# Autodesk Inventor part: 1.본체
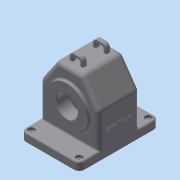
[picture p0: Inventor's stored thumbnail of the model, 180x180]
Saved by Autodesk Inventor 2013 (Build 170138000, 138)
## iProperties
Created: 2016-12
Part Number: 1.본체
Material: 일반
Document SubType Name: Modeling
Designer: Administrator
Density: 1 g/cm^3
Author: Administrator
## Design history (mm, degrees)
sketch "스케치1"
  geometry: L1 (-55, 80)-(-55, 0); L2 (-55, 0)-(55, 0); L3 (55, 0)-(55, 80); L4 (55, 80)-(23.491, 125); L5 (23.491, 125)-(-23.491, 125); L6 (-23.491, 125)-(-55, 80); 3 further points
  constraints: 12 end point, 2 midpoint, 2 parallel, 1 coincident, 1 perpendicular, 1 vertical, 1 vertical alignment
  dimensions: "d0" = 110 distance of L1.end L2.end; "d2" = 80 distance of L2.end L3.end; "d3" = 80 distance of L1.start L1.end; "d4" = 125 distance between parallel lines of L2 L5; "d5" = 35 deg angle of L6 L1; "d6" = 35 deg angle of L4 L3 (derived)
extrude "돌출1" new body sketch "스케치1" stored distance "d7" = 77; taper "d8" = 0 deg
feature "쉘1" dims "d9" = 5
sketch "스케치2"
  geometry: L1 (78.424, 33.5)-(0, 33.5) reference; L2 (80, 38.5)-(0, 38.5) reference; L3 (0, -33.5)-(78.424, -33.5) reference; L4 (0, -38.5)-(80, -38.5) reference; L5 (65, 33.5)-(65, -33.5); L6 (120, 33.5)-(78.424, 33.5) reference; L7 (125, 38.5)-(80, 38.5) reference; L8 (65, 33.5)-(65, 19.5); L9 (65, 19.5)-(92, 19.5); L10 (92, 19.5)-(106, 33.5); 1 further point
  constraints: 8 end point, 4 point on line, 2 perpendicular
  dimensions: "d10" = 65 distance from line of L5 point (0, 0); "d12" = 14 distance between parallel lines of L1 L9; "d13" = 54 diameter of L9.end L5; "d14" = 45 deg angle of L10 L9
revolve "회전1" sketch "스케치2" stored, may be unused: angle "d15" = 90 deg
sketch "스케치3"
  geometry: L1 (-55, 0)-(55, 0) reference; C1 r 37.5 at (0, 65); 2 further points
  constraints: 1 centre point, 1 midpoint, 1 vertical alignment
  dimensions: "d16" = 65 distance of point (0, 0) C1.centre; "d17" = 75 diameter of C1
extrude "돌출2" join sketch "스케치3" distance "d18" = 5; taper "d19" = 0 deg
sketch "스케치4"
  geometry: L1 (-55, 0)-(55, 0) reference; C1 r 31 at (0, 65); 2 further points
  constraints: 1 centre point, 1 midpoint, 1 vertical alignment
  dimensions: "d20" = 65 distance of point (0, 0) C1.centre; "d21" = 62 diameter of C1
extrude "돌출3" join sketch "스케치4" distance "d22" = 10; taper "d23" = 0 deg
hole "구멍1" diameter "d26" = 40; stored, may be unused: countersink angle "d30" = 90 deg, drill point angle "d32" = 118 deg; dims "d24" = 10, "d25" = 10, "d27" = 6, "d28" = 4, "d29" = 2, "d31" = 8
sketch "스케치5" dims "d33" = 58
  geometry: C1 r 20 at (0, 0) reference; 3 further points
  constraints: 2 vertical alignment, 1 coincident, 2 other
hole "구멍2" sketch "스케치5" at (0, 29) diameter "d35" = 2.459; stored, may be unused: countersink angle "d39" = 90 deg, drill point angle "d41" = 118 deg; dims "d36" = 6, "d37" = 4, "d38" = 2, "d40" = 8
sketch "스케치6" dims "d45" = 52
  geometry: C1 r 20 at (0, 0) reference; 3 further points
  constraints: 2 vertical alignment, 1 coincident, 2 other
hole "구멍3" sketch "스케치6" at (0, 26) diameter "d47" = 2.459; stored, may be unused: countersink angle "d51" = 90 deg, drill point angle "d53" = 118 deg; dims "d48" = 6, "d49" = 4, "d50" = 2, "d52" = 8
chamfer "모따기1" distance "d57" = 1; stored, may be unused: second distance "d58" = 2, angle "d59" = 45 deg
sketch "스케치7"
  geometry: L1 (110, -77)-(110, 0) reference; L2 (105, -5)-(105, -72) reference; L3 (105, -72)-(5, -72) reference; L4 (5, -72)-(5, -5) reference; L5 (5, -5)-(105, -5) reference; L6 (110, -77)-(110, 0) reference; L7 (0, 0)-(110, 0) reference; L8 (0, -77)-(0, 0) reference; L9 (110, -77)-(0, -77) reference; L10 (0, 36.5)-(110, 36.5); L11 (110, 36.5)-(110, -113.5); L12 (110, -113.5)-(0, -113.5); L13 (0, -113.5)-(0, 36.5); L14 (0, 36.5)-(110, -113.5); 2 further points
  constraints: 10 end point, 2 parallel, 1 coincident, 1 horizontal, 1 midpoint, 1 perpendicular
  dimensions: "d60" = 150 distance of L12.end L10.start; "d62" = 110 distance of L11.end L12.end
extrude "돌출4" join sketch "스케치7" distance "d63" = 15; taper "d64" = 0 deg
fillet "모깎기1" dims "d65" = 10
sketch "스케치8"
  geometry: L1 (10, -36.5)-(100, -36.5) reference; L2 (110, -26.5)-(110, 0) reference; L3 (0, 0)-(110, 0) reference; L4 (0, 0)-(0, -26.5) reference; L5 (0, 103.5)-(0, 77) reference; L6 (110, 77)-(0, 77) reference; L7 (110, 77)-(110, 103.5) reference; L8 (100, 113.5)-(10, 113.5) reference; A1 r 10 centre (10, -26.5) between (0, -26.5) and (10, -36.5) reference; A2 r 10 centre (100, -26.5) between (100, -36.5) and (110, -26.5) reference; A3 r 10 centre (10, 103.5) between (10, 113.5) and (0, 103.5) reference; A4 r 10 centre (100, 103.5) between (110, 103.5) and (100, 113.5) reference; 1 further point
hole "구멍4" sketch "스케치8" at (10, -26.5), (100, -26.5), (100, 103.5), (10, 103.5) diameter "d66" = 5; stored, may be unused: countersink angle "d70" = 90 deg, drill point angle "d72" = 0 deg; dims "d67" = 6, "d68" = 12, "d69" = 5, "d71" = 8
fillet "모깎기2" dims "d73" = 10
fillet "모깎기3" dims "d74" = 8
node "작업 평면1"
sketch "스케치9"
  geometry: L1 (-18.285, 125)-(18.285, 125) reference; L2 (-7.5, 125)-(-7.5, 135); L3 (-7.5, 135)-(7.5, 135); L4 (7.5, 135)-(7.5, 125); L5 (-12.5, 125)-(-12.5, 140); L6 (-12.5, 140)-(12.5, 140); L7 (12.5, 140)-(12.5, 125); L8 (50, 0)-(-50, 0) reference; 3 further points
  constraints: 12 end point, 5 perpendicular, 4 point on line, 2 midpoint, 2 vertical alignment, 1 parallel
  dimensions: "d76" = 25 distance of L5.end L6.end; "d78" = 15 distance of L2.end L3.end; "d79" = 140 distance between parallel lines of L6 L8; "d80" = 5 distance between parallel lines of L3 L6
extrude "돌출5" join sketch "스케치9" distance "d81" = 8; taper "d82" = 0 deg
fillet "모깎기4" dims "d83" = 8
fillet "모깎기5" dims "d84" = 3
fillet "모깎기6" dims "d85" = 1
fillet "모깎기7" dims "d86" = 1
fillet "모깎기8" dims "d87" = 1
fillet "모깎기9" dims "d88" = 3
fillet "모깎기10" dims "d89" = 3
fillet "모깎기11" dims "d90" = 3
fillet "모깎기12" dims "d91" = 3
fillet "모깎기13" dims "d92" = 5
fillet "모깎기14" dims "d93" = 3
sketch "스케치10"
  geometry: L1 (26.5, 76.847)-(26.5, 18) reference; L2 (130, 0)-(0, 0) reference; 2 further points
  constraints: 1 other
  dimensions: "d94" = 38.5 distance from line of point (65, 45) L1; "d95" = 45 distance from line of point (65, 45) L2
feature "엠보싱1" sketch "스케치10" dims "d96" = 0.5, "d97" = 0
node "솔리드1"
pattern_circular "원형 패턴1" dims angle "d43" = 360 deg
pattern_circular "원형 패턴2" dims angle "d55" = 360 deg
mirror "대칭1"
node "투영된 루프1"
node "투영된 루프2"
node "투영된 루프3"
other parameters: "d75" = -18
